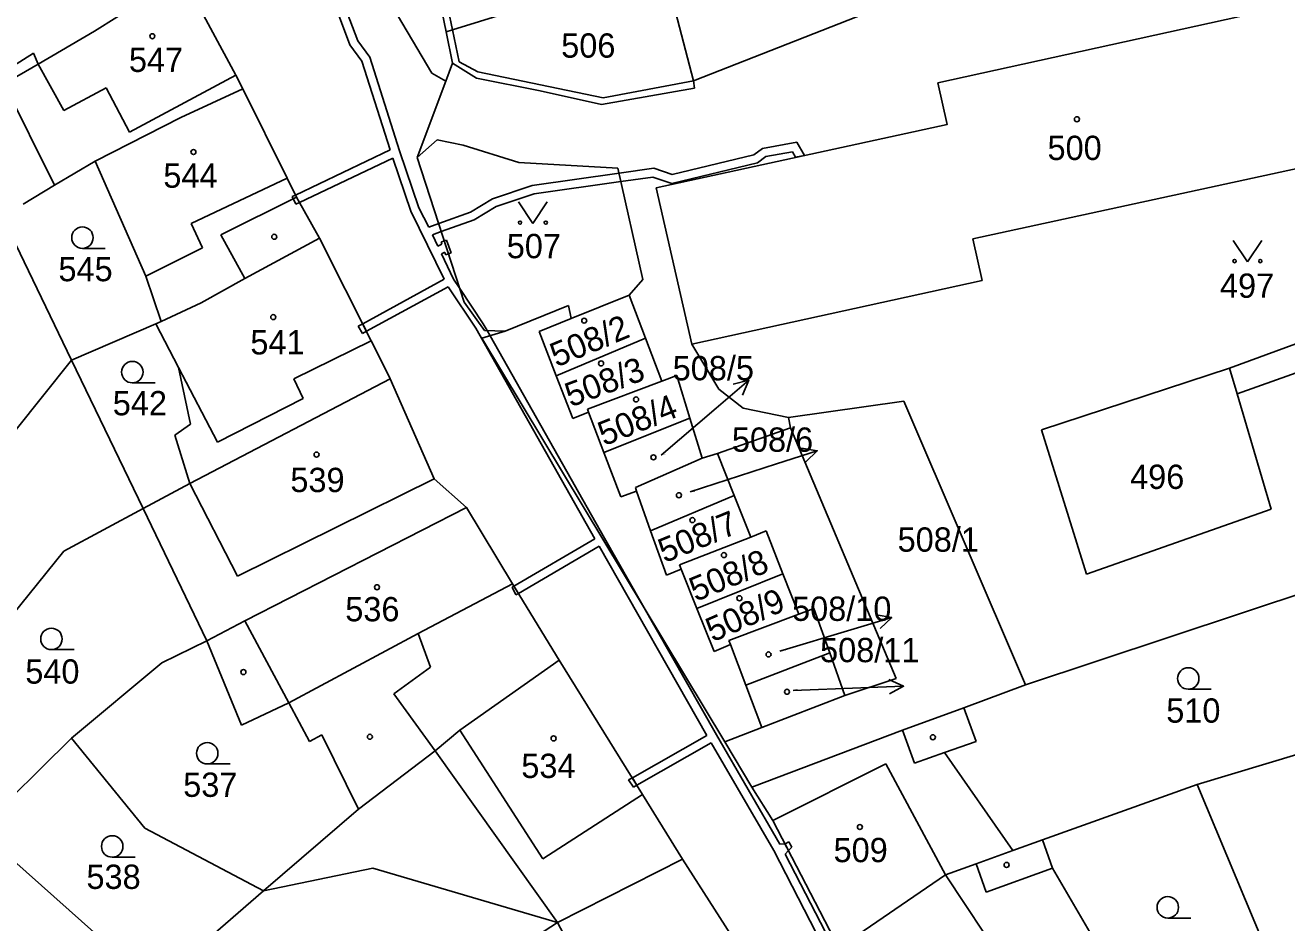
# Model space of a CAD drawing. Extents: x -785744 to -782822, y -1067550 to -1063910.
# Drawn here: x -783737.6 to -783649.3, y -1065623.4 to -1065560.7 of the extents above; entities that cross this region are included whole.
import ezdxf

# ---------------------------------------------------------------- set-up
doc = ezdxf.new("R2010")
doc.units = 0
for name, color, linetype in [('Hranice parcel', 7, 'Continuous'), ('Parcelní čísla', 7, 'Continuous'), ('Pop_ČP_popisy', 7, 'Continuous'), ('Vnitřní kresba', 7, 'Continuous'), ('Věcná břemena k části', 7, 'Continuous'), ('Značky budov', 7, 'Continuous'), ('Značky kultur', 7, 'Continuous')]:
    doc.layers.add(name, color=color, linetype=linetype)

msp = doc.modelspace()

# ---------------------------------------------------------------- linework, layer by layer
at = {"layer": 'Hranice parcel'}
for p, q in [((-783716.96, -1065575.54), (-783713.34, -1065582.73)), ((-783728.41, -1065581.54), (-783728.04, -1065581.38)), ((-783728.41, -1065581.54), (-783734.31, -1065584.09)), ((-783726.82, -1065584.6), (-783728.41, -1065581.54)), ((-783713.34, -1065582.73), (-783712.51, -1065584.38)), ((-783726.82, -1065584.6), (-783726, -1065588.56))]:
    msp.add_line(p, q, dxfattribs=at)
for points in [[(-783692.88, -1065556.48), (-783690.8, -1065564.53)], [(-783726.53, -1065557.25), (-783722.81, -1065564.14)], [(-783707.66, -1065560.97), (-783695.33, -1065557.14)], [(-783673.7, -1065564.67), (-783639.49, -1065557.16)], [(-783732.71, -1065561.07), (-783728.03, -1065558.1)], [(-783708.71, -1065558.16), (-783708.1, -1065561.11)], [(-783690.8, -1065564.53), (-783675.21, -1065558.4)], [(-783736.66, -1065563.38), (-783732.71, -1065561.07)], [(-783708.1, -1065561.11), (-783707.66, -1065560.97)], [(-783708.1, -1065561.11), (-783707.65, -1065563.31)], [(-783739.35, -1065564.1), (-783736.98, -1065562.6)], [(-783736.98, -1065562.6), (-783736.66, -1065563.38)], [(-783739.03, -1065564.74), (-783736.66, -1065563.38)], [(-783708.12, -1065564.56), (-783707.65, -1065563.31)], [(-783707.65, -1065563.31), (-783705.98, -1065564.35)], [(-783722.81, -1065564.14), (-783722.33, -1065565.09)], [(-783710.12, -1065569.9), (-783708.12, -1065564.56)], [(-783705.98, -1065564.35), (-783701.52, -1065565.23)], [(-783693.41, -1065572.02), (-783673.04, -1065567.59), (-783673.7, -1065564.67)], [(-783690.8, -1065564.53), (-783690.72, -1065565.05)], [(-783739.03, -1065564.74), (-783735.5, -1065571.85)], [(-783726.66, -1065567.1), (-783722.33, -1065565.09)], [(-783722.33, -1065565.09), (-783719.23, -1065571.34)], [(-783701.52, -1065565.23), (-783697.22, -1065566.19)], [(-783697.22, -1065566.19), (-783690.72, -1065565.05)], [(-783732.67, -1065570.15), (-783726.66, -1065567.1)], [(-783671.24, -1065575.59), (-783637.06, -1065568.18)], [(-783710.12, -1065569.9), (-783708.72, -1065568.67)], [(-783708.72, -1065568.67), (-783706.9, -1065569.03)], [(-783706.9, -1065569.03), (-783703.01, -1065570.26)], [(-783710.12, -1065569.9), (-783706.84, -1065580.03)], [(-783735.5, -1065571.85), (-783732.67, -1065570.15)], [(-783732.67, -1065570.15), (-783729.12, -1065578.2)], [(-783703.01, -1065570.26), (-783696.08, -1065570.65)], [(-783696.08, -1065570.65), (-783694.34, -1065578.44)], [(-783719.23, -1065571.34), (-783718.58, -1065572.68)], [(-783737.69, -1065573.18), (-783735.5, -1065571.85)], [(-783693.41, -1065572.02), (-783690.91, -1065582.97)], [(-783718.58, -1065572.68), (-783716.96, -1065575.54)], [(-783738.82, -1065574.73), (-783734.31, -1065584.09)], [(-783722.18, -1065578.36), (-783716.96, -1065575.54)], [(-783671.24, -1065575.59), (-783670.59, -1065578.52)], [(-783729.12, -1065578.2), (-783728.04, -1065581.38)], [(-783725.25, -1065580.06), (-783722.18, -1065578.36)], [(-783695.29, -1065579.53), (-783694.34, -1065578.44)], [(-783690.91, -1065582.97), (-783670.59, -1065578.52)], [(-783699.35, -1065581.17), (-783695.29, -1065579.53)], [(-783695.29, -1065579.53), (-783694.14, -1065582.54)], [(-783728.04, -1065581.38), (-783725.25, -1065580.06)], [(-783706.84, -1065580.03), (-783705.41, -1065582)], [(-783703.98, -1065582.06), (-783699.55, -1065580.25)], [(-783699.55, -1065580.25), (-783699.35, -1065581.17)], [(-783701.6, -1065582.08), (-783699.35, -1065581.17)], [(-783705.6, -1065582.54), (-783703.98, -1065582.06)], [(-783705.41, -1065582), (-783703.98, -1065582.06)], [(-783701.6, -1065582.08), (-783700.4, -1065585.17)], [(-783705.6, -1065582.54), (-783688.61, -1065610.77)], [(-783700.4, -1065585.17), (-783694.14, -1065582.54)], [(-783694.14, -1065582.54), (-783693, -1065585.54)], [(-783690.91, -1065582.97), (-783689.01, -1065586.1)], [(-783751.85, -1065606.03), (-783734.31, -1065584.09)], [(-783734.31, -1065584.09), (-783729.3, -1065594.46)], [(-783712.51, -1065584.38), (-783712.01, -1065585.39)], [(-783666.45, -1065588.96), (-783653.29, -1065584.63)], [(-783653.29, -1065584.63), (-783652.75, -1065586.43)], [(-783726.03, -1065592.7), (-783712.01, -1065585.39)], [(-783712.01, -1065585.39), (-783708.94, -1065592.38)], [(-783700.4, -1065585.17), (-783699.24, -1065588.16)], [(-783698.21, -1065587.51), (-783693, -1065585.54)], [(-783693, -1065585.54), (-783691.96, -1065585.15)], [(-783691.96, -1065585.15), (-783691.04, -1065588.15)], [(-783689.01, -1065586.1), (-783687.32, -1065587.43)], [(-783652.75, -1065586.43), (-783650.38, -1065594.51)], [(-783698.21, -1065587.51), (-783698.13, -1065587.73)], [(-783687.32, -1065587.43), (-783684.14, -1065588.1)], [(-783684.14, -1065588.1), (-783676.07, -1065586.95)], [(-783676.07, -1065586.95), (-783667.55, -1065606.8)], [(-783699.24, -1065588.16), (-783698.13, -1065587.73)], [(-783698.13, -1065587.73), (-783697.06, -1065590.53)], [(-783697.06, -1065590.53), (-783691.04, -1065588.15)], [(-783691.04, -1065588.15), (-783690.19, -1065590.94)], [(-783684.14, -1065588.1), (-783684.01, -1065588.82)], [(-783727.08, -1065589.33), (-783726, -1065588.56)], [(-783727.08, -1065589.33), (-783726.03, -1065592.7)], [(-783689.11, -1065590.62), (-783684.01, -1065588.82)], [(-783666.45, -1065588.96), (-783663.3, -1065599.05)], [(-783697.06, -1065590.53), (-783695.88, -1065593.64)], [(-783694.85, -1065592.99), (-783690.19, -1065590.94)], [(-783690.19, -1065590.94), (-783689.11, -1065590.62)], [(-783689.11, -1065590.62), (-783687.95, -1065593.54)], [(-783729.3, -1065594.46), (-783726.03, -1065592.7)], [(-783708.94, -1065592.38), (-783706.67, -1065594.39)], [(-783695.88, -1065593.64), (-783694.77, -1065593.24)], [(-783694.85, -1065592.99), (-783694.77, -1065593.24)], [(-783694.77, -1065593.24), (-783693.79, -1065596.01)], [(-783693.79, -1065596.01), (-783687.95, -1065593.54)], [(-783687.95, -1065593.54), (-783686.79, -1065596.46)], [(-783734.85, -1065597.44), (-783729.3, -1065594.46)], [(-783729.3, -1065594.46), (-783724.85, -1065603.71)], [(-783722.19, -1065602.31), (-783706.67, -1065594.39)], [(-783706.67, -1065594.39), (-783703.45, -1065599.73)], [(-783663.3, -1065599.05), (-783650.38, -1065594.51)], [(-783693.79, -1065596.01), (-783692.69, -1065599.13)], [(-783691.78, -1065598.41), (-783686.79, -1065596.46)], [(-783686.79, -1065596.46), (-783685.71, -1065596.03)], [(-783685.71, -1065596.03), (-783684.53, -1065599.03)], [(-783745.75, -1065610.93), (-783734.85, -1065597.44)], [(-783692.69, -1065599.13), (-783691.66, -1065598.71)], [(-783691.78, -1065598.41), (-783691.66, -1065598.71)], [(-783691.66, -1065598.71), (-783690.55, -1065601.46)], [(-783690.55, -1065601.46), (-783684.53, -1065599.03)], [(-783684.53, -1065599.03), (-783683.42, -1065601.86)], [(-783667.55, -1065606.8), (-783642.32, -1065598.43)], [(-783703.45, -1065599.73), (-783700.19, -1065605.06)], [(-783690.55, -1065601.46), (-783689.34, -1065604.47)], [(-783683.42, -1065601.86), (-783682.36, -1065601.45)], [(-783682.36, -1065601.45), (-783681.26, -1065604.55)], [(-783724.85, -1065603.71), (-783722.19, -1065602.31)], [(-783688.31, -1065603.7), (-783683.42, -1065601.86)], [(-783727.99, -1065605.25), (-783724.85, -1065603.71)], [(-783724.85, -1065603.71), (-783722.42, -1065609.61)], [(-783689.34, -1065604.47), (-783688.2, -1065603.98)], [(-783688.31, -1065603.7), (-783688.2, -1065603.98)], [(-783688.2, -1065603.98), (-783687.13, -1065606.82)], [(-783734.32, -1065610.53), (-783727.99, -1065605.25)], [(-783707.14, -1065609.96), (-783700.19, -1065605.06)], [(-783700.19, -1065605.06), (-783694.35, -1065614.47)], [(-783687.13, -1065606.82), (-783681.26, -1065604.55)], [(-783681.26, -1065604.55), (-783680.2, -1065607.55)], [(-783687.13, -1065606.82), (-783686.02, -1065609.78)], [(-783671.88, -1065608.41), (-783667.55, -1065606.8)], [(-783686.02, -1065609.78), (-783680.2, -1065607.55)], [(-783722.42, -1065609.61), (-783719.12, -1065608.06)], [(-783719.12, -1065608.06), (-783717.67, -1065610.76)], [(-783676.16, -1065609.96), (-783671.88, -1065608.41)], [(-783671.88, -1065608.41), (-783671.02, -1065610.76)], [(-783655.55, -1065613.76), (-783638.72, -1065608.7)], [(-783740.75, -1065616.87), (-783734.32, -1065610.53)], [(-783734.32, -1065610.53), (-783729.19, -1065616.81)], [(-783717.67, -1065610.76), (-783716.79, -1065610.28)], [(-783716.79, -1065610.28), (-783714.24, -1065615.48)], [(-783708.86, -1065611.42), (-783707.14, -1065609.96)], [(-783686.7, -1065613.96), (-783676.16, -1065609.96)], [(-783714.24, -1065615.48), (-783708.86, -1065611.42)], [(-783688.61, -1065610.77), (-783686.7, -1065613.96)], [(-783673.23, -1065611.53), (-783671.02, -1065610.76)], [(-783673.23, -1065611.53), (-783668.44, -1065618.38)], [(-783686.7, -1065613.96), (-783685.23, -1065616.29)], [(-783666.37, -1065617.64), (-783655.55, -1065613.76)], [(-783655.55, -1065613.76), (-783649.44, -1065628.38)], [(-783694.35, -1065614.47), (-783691.55, -1065619)], [(-783720.87, -1065621.21), (-783714.24, -1065615.48)], [(-783685.23, -1065616.29), (-783680.61, -1065625.18)], [(-783740.32, -1065617.38), (-783731.67, -1065625.04)], [(-783729.19, -1065616.81), (-783720.87, -1065621.21)], [(-783668.44, -1065618.38), (-783666.37, -1065617.64)], [(-783666.37, -1065617.64), (-783665.66, -1065619.61)], [(-783671.02, -1065619.31), (-783668.44, -1065618.38)], [(-783700.3, -1065623.43), (-783691.55, -1065619)], [(-783691.55, -1065619), (-783686.72, -1065626.56)], [(-783673.15, -1065620.08), (-783671.02, -1065619.31)], [(-783720.87, -1065621.21), (-783713.22, -1065619.62)], [(-783713.22, -1065619.62), (-783700.3, -1065623.43)], [(-783680.61, -1065625.18), (-783673.15, -1065620.08)], [(-783665.66, -1065619.61), (-783658.15, -1065632.49)], [(-783728.52, -1065627.83), (-783720.87, -1065621.21)], [(-783705.51, -1065626.79), (-783700.3, -1065623.43)], [(-783700.3, -1065623.43), (-783696.36, -1065630.89)]]:
    msp.add_lwpolyline(points, dxfattribs=at)
at = {"layer": 'Pop_ČP_popisy'}
for p, q in [((-783689.21, -1065587.44), (-783686.929, -1065585.491)), ((-783684.98, -1065591.34), (-783682.127, -1065590.413)), ((-783679.79, -1065602.95), (-783676.915, -1065602.092)), ((-783679.09, -1065607.01), (-783676.092, -1065606.89))]:
    msp.add_line(p, q, dxfattribs=at)
for points in [[(-783688.014, -1065585.761), (-783686.929, -1065585.491), (-783687.365, -1065586.521)], [(-783693.05, -1065590.72), (-783689.21, -1065587.44)], [(-783683.232, -1065590.247), (-783682.127, -1065590.413), (-783682.923, -1065591.198)], [(-783691.03, -1065593.3), (-783684.98, -1065591.34)], [(-783678.017, -1065601.899), (-783676.915, -1065602.092), (-783677.731, -1065602.857)], [(-783684.75, -1065604.43), (-783679.79, -1065602.95)], [(-783683.82, -1065607.2), (-783679.09, -1065607.01)], [(-783677.112, -1065606.43), (-783676.092, -1065606.89), (-783677.072, -1065607.429)]]:
    msp.add_lwpolyline(points, dxfattribs=at)
at = {"layer": 'Vnitřní kresba'}
for p, q in [((-783713.34, -1065582.73), (-783718.76, -1065585.39)), ((-783724.11, -1065589.82), (-783726.82, -1065584.6)), ((-783718.76, -1065585.39), (-783718.11, -1065586.76)), ((-783718.11, -1065586.76), (-783724.11, -1065589.82))]:
    msp.add_line(p, q, dxfattribs=at)
for points in [[(-783708.26, -1065558.07), (-783707.66, -1065560.97)], [(-783712.18, -1065558.78), (-783709.11, -1065564)], [(-783707.66, -1065560.97), (-783707.2, -1065563.21)], [(-783736.66, -1065563.38), (-783734.86, -1065566.62)], [(-783707.2, -1065563.21), (-783705.88, -1065563.91)], [(-783730.26, -1065568.13), (-783722.81, -1065564.14)], [(-783709.11, -1065564), (-783708.12, -1065564.56)], [(-783705.88, -1065563.91), (-783697.12, -1065565.74)], [(-783697.12, -1065565.74), (-783690.8, -1065564.53)], [(-783734.86, -1065566.62), (-783731.88, -1065565.04)], [(-783731.88, -1065565.04), (-783730.26, -1065568.13)], [(-783725.94, -1065574.53), (-783719.23, -1065571.34)], [(-783723.87, -1065575.32), (-783718.58, -1065572.68)], [(-783725.94, -1065574.53), (-783725.14, -1065576.23)], [(-783723.87, -1065575.32), (-783722.18, -1065578.36)], [(-783729.12, -1065578.2), (-783725.14, -1065576.23)], [(-783653.29, -1065584.63), (-783634.71, -1065577.84)], [(-783652.75, -1065586.43), (-783634.47, -1065579.93)], [(-783684.01, -1065588.82), (-783676.6, -1065606.35)], [(-783726.03, -1065592.7), (-783722.71, -1065599.19)], [(-783722.71, -1065599.19), (-783708.94, -1065592.38)], [(-783710.05, -1065603.2), (-783703.45, -1065599.73)], [(-783722.19, -1065602.31), (-783719.12, -1065608.06)], [(-783719.12, -1065608.06), (-783710.05, -1065603.2)], [(-783710.05, -1065603.2), (-783709.2, -1065605.55)], [(-783711.77, -1065607.43), (-783709.2, -1065605.55)], [(-783680.2, -1065607.55), (-783676.6, -1065606.35)], [(-783711.77, -1065607.43), (-783708.86, -1065611.42)], [(-783707.14, -1065609.96), (-783701.33, -1065618.97)], [(-783688.61, -1065610.77), (-783686.02, -1065609.78)], [(-783676.16, -1065609.96), (-783675.32, -1065612.27)], [(-783708.86, -1065611.42), (-783700.3, -1065623.43)], [(-783685.23, -1065616.29), (-783677.33, -1065612.31)], [(-783677.33, -1065612.31), (-783673.15, -1065620.08)], [(-783675.32, -1065612.27), (-783673.23, -1065611.53)], [(-783701.33, -1065618.97), (-783694.35, -1065614.47)], [(-783671.02, -1065619.31), (-783670.31, -1065621.29)], [(-783673.15, -1065620.08), (-783664.99, -1065632.4)], [(-783670.31, -1065621.29), (-783665.66, -1065619.61)]]:
    msp.add_lwpolyline(points, dxfattribs=at)
at = {"layer": 'Věcná břemena k části'}
for points in [[(-783714.29, -1065561.75), (-783715.84, -1065557.61)], [(-783716.42, -1065557.75), (-783714.83, -1065562.03)], [(-783714.83, -1065562.03), (-783713.99, -1065563.16)], [(-783713.45, -1065562.88), (-783714.29, -1065561.75)], [(-783711.37, -1065569.44), (-783713.45, -1065562.88)], [(-783713.99, -1065563.16), (-783712.02, -1065569.37)], [(-783683.56, -1065568.84), (-783685.96, -1065569.28)], [(-783683.03, -1065569.76), (-783683.56, -1065568.84)], [(-783712.02, -1065569.37), (-783718.65, -1065572.53)], [(-783718.36, -1065573.06), (-783711.83, -1065569.95)], [(-783711.83, -1065569.95), (-783710.56, -1065573.67)], [(-783710, -1065573.43), (-783711.37, -1065569.44)], [(-783686.57, -1065569.71), (-783692.28, -1065571.1)], [(-783685.96, -1065569.28), (-783686.57, -1065569.71)], [(-783686.31, -1065570.27), (-783685.72, -1065569.84)], [(-783685.72, -1065569.84), (-783683.87, -1065569.51)], [(-783683.87, -1065569.51), (-783683.65, -1065569.89)], [(-783683.65, -1065569.89), (-783683.03, -1065569.76)], [(-783693.57, -1065570.66), (-783696, -1065571)], [(-783692.28, -1065571.1), (-783693.57, -1065570.66)], [(-783692.3, -1065571.72), (-783686.31, -1065570.27)], [(-783696, -1065571), (-783702.09, -1065571.86)], [(-783701.95, -1065572.44), (-783695.87, -1065571.59)], [(-783695.87, -1065571.59), (-783693.63, -1065571.28)], [(-783693.63, -1065571.28), (-783692.3, -1065571.72)], [(-783718.65, -1065572.53), (-783718.88, -1065572.64)], [(-783718.88, -1065572.64), (-783718.61, -1065573.18)], [(-783718.65, -1065572.53), (-783718.58, -1065572.68)], [(-783718.58, -1065572.68), (-783718.65, -1065572.53)], [(-783702.09, -1065571.86), (-783704.85, -1065572.8)], [(-783704.59, -1065573.34), (-783701.95, -1065572.44)], [(-783718.61, -1065573.18), (-783718.36, -1065573.06)], [(-783718.58, -1065572.68), (-783718.36, -1065573.06)], [(-783718.36, -1065573.06), (-783718.58, -1065572.68)], [(-783709.32, -1065574.78), (-783710, -1065573.43)], [(-783704.85, -1065572.8), (-783706.39, -1065573.72)], [(-783706.13, -1065574.26), (-783704.59, -1065573.34)], [(-783710.56, -1065573.67), (-783708.25, -1065578.41)], [(-783706.39, -1065573.72), (-783708.62, -1065574.53)], [(-783708.44, -1065575.09), (-783706.13, -1065574.26)], [(-783708.62, -1065574.53), (-783709.32, -1065574.78)], [(-783709.06, -1065575.32), (-783708.44, -1065575.09)], [(-783708.68, -1065576.11), (-783709.06, -1065575.32)], [(-783708.41, -1065575.97), (-783708.68, -1065576.11)], [(-783708.23, -1065575.74), (-783708.46, -1065575.83)], [(-783708.46, -1065575.83), (-783708.41, -1065575.97)], [(-783708.08, -1065575.69), (-783708.23, -1065575.74)], [(-783707.76, -1065576.57), (-783708.08, -1065575.69)], [(-783708.43, -1065576.64), (-783708.2, -1065576.53)], [(-783707.59, -1065578.41), (-783708.43, -1065576.64)], [(-783708.2, -1065576.53), (-783708.14, -1065576.71)], [(-783708.14, -1065576.71), (-783707.94, -1065576.64)], [(-783707.94, -1065576.64), (-783707.76, -1065576.57)], [(-783708.25, -1065578.41), (-783713.94, -1065581.53)], [(-783707.15, -1065579.07), (-783707.59, -1065578.41)], [(-783713.68, -1065582.06), (-783707.96, -1065578.94)], [(-783707.96, -1065578.94), (-783706.03, -1065581.85)], [(-783705.51, -1065581.53), (-783707.15, -1065579.07)], [(-783713.94, -1065581.53), (-783714.25, -1065581.7)], [(-783714.25, -1065581.7), (-783713.96, -1065582.22)], [(-783713.96, -1065582.22), (-783713.68, -1065582.06)], [(-783713.94, -1065581.53), (-783713.68, -1065582.06)], [(-783713.68, -1065582.06), (-783713.94, -1065581.53)], [(-783706.03, -1065581.85), (-783697.7, -1065596.58)], [(-783705.24, -1065582.01), (-783705.51, -1065581.53)], [(-783705.03, -1065582.37), (-783705.24, -1065582.01)], [(-783697.03, -1065596.54), (-783705.03, -1065582.37)], [(-783697.7, -1065596.58), (-783703.36, -1065599.88)], [(-783703.04, -1065600.4), (-783697.4, -1065597.1)], [(-783697.4, -1065597.1), (-783689.86, -1065610.33)], [(-783694.43, -1065601.09), (-783697.03, -1065596.54)], [(-783703.36, -1065599.88), (-783703.47, -1065599.95)], [(-783703.47, -1065599.95), (-783703.22, -1065600.5)], [(-783703.36, -1065599.88), (-783703.04, -1065600.4)], [(-783703.04, -1065600.4), (-783703.36, -1065599.88)], [(-783703.22, -1065600.5), (-783703.04, -1065600.4)], [(-783689.19, -1065610.29), (-783694.43, -1065601.09)], [(-783689.86, -1065610.33), (-783695.07, -1065613.3)], [(-783684.75, -1065617.93), (-783689.19, -1065610.29)], [(-783694.75, -1065613.82), (-783689.56, -1065610.85)], [(-783689.56, -1065610.85), (-783685.18, -1065618.38)], [(-783695.07, -1065613.3), (-783695.33, -1065613.45)], [(-783695.33, -1065613.45), (-783695, -1065613.96)], [(-783695.07, -1065613.3), (-783694.75, -1065613.82)], [(-783694.75, -1065613.82), (-783695.07, -1065613.3)], [(-783695, -1065613.96), (-783694.75, -1065613.82)], [(-783685.18, -1065618.38), (-783681.34, -1065625.82)], [(-783684.38, -1065617.92), (-783684.75, -1065617.93)], [(-783684.13, -1065617.78), (-783684.38, -1065617.92)], [(-783684.14, -1065618.38), (-783684.38, -1065617.92)], [(-783684.38, -1065617.92), (-783684.14, -1065618.38)], [(-783684.38, -1065618.63), (-783684.14, -1065618.38)], [(-783684.14, -1065618.38), (-783683.92, -1065618.15)], [(-783683.92, -1065618.15), (-783684.13, -1065617.78)], [(-783680.84, -1065625.5), (-783684.38, -1065618.63)]]:
    msp.add_lwpolyline(points, dxfattribs=at)
at = {"layer": 'Značky budov'}
for centre in [(-783728.66, -1065561.42), (-783663.96, -1065567.23), (-783725.78, -1065569.52), (-783720.13, -1065575.45), (-783720.2, -1065581.07), (-783698.44, -1065581.32), (-783697.26, -1065584.31), (-783694.81, -1065586.83), (-783717.17, -1065590.69), (-783693.6, -1065590.88), (-783691.81, -1065593.53), (-783690.87, -1065595.27), (-783688.66, -1065597.72), (-783712.94, -1065599.97), (-783687.58, -1065600.74), (-783685.54, -1065604.67), (-783722.29, -1065605.9), (-783684.25, -1065607.28), (-783713.44, -1065610.43), (-783700.58, -1065610.54), (-783674.04, -1065610.46), (-783679.15, -1065616.74), (-783668.88, -1065619.39)]:
    msp.add_circle(centre, 0.175, dxfattribs=at)
at = {"layer": 'Značky kultur'}
for p, q in [((-783703.03, -1065573.01), (-783702.03, -1065574.51)), ((-783702.03, -1065574.51), (-783701.03, -1065573.01)), ((-783653.03, -1065575.7), (-783652.03, -1065577.2)), ((-783652.03, -1065577.2), (-783651.03, -1065575.7)), ((-783733.55, -1065576.26), (-783731.95, -1065576.26)), ((-783730.06, -1065585.67), (-783728.46, -1065585.67)), ((-783735.72, -1065604.33), (-783734.12, -1065604.33)), ((-783656.17, -1065607.1), (-783654.57, -1065607.1)), ((-783724.82, -1065612.33), (-783723.22, -1065612.33)), ((-783731.47, -1065618.85), (-783729.87, -1065618.85)), ((-783657.6, -1065623.11), (-783656, -1065623.11))]:
    msp.add_line(p, q, dxfattribs=at)
for centre, radius in [((-783702.93, -1065574.46), 0.112), ((-783701.13, -1065574.46), 0.112), ((-783733.55, -1065575.51), 0.75), ((-783652.93, -1065577.15), 0.112), ((-783651.13, -1065577.15), 0.112), ((-783730.06, -1065584.92), 0.75), ((-783735.72, -1065603.58), 0.75), ((-783656.17, -1065606.35), 0.75), ((-783724.82, -1065611.58), 0.75), ((-783731.47, -1065618.1), 0.75), ((-783657.6, -1065622.36), 0.75)]:
    msp.add_circle(centre, radius, dxfattribs=at)

# ---------------------------------------------------------------- texts
at = {"layer": 'Parcelní čísla'}
for s, height, p in [('506', 1.7, (-783700.05, -1065562.92)), ('547', 1.7, (-783730.3, -1065563.92)), ('500', 1.7, (-783666.02, -1065570.08)), ('544', 1.7, (-783727.89, -1065572.02)), ('507', 1.7, (-783703.86, -1065576.95)), ('545', 1.7, (-783735.23, -1065578.56)), ('497', 1.7, (-783653.95, -1065579.72)), ('541', 1.7, (-783721.8, -1065583.68)), ('542', 1.7, (-783731.43, -1065587.94)), ('508/5', 0.1, (-783693.05, -1065590.72)), ('539', 1.7, (-783719, -1065593.31)), ('496', 1.7, (-783660.24, -1065593.09)), ('508/6', 0.1, (-783691.03, -1065593.3)), ('508/1', 1.7, (-783676.51, -1065597.48)), ('536', 1.7, (-783715.16, -1065602.35)), ('508/10', 0.1, (-783684.75, -1065604.43)), ('540', 1.7, (-783737.55, -1065606.71)), ('508/11', 0.1, (-783683.82, -1065607.2)), ('510', 1.7, (-783657.71, -1065609.44)), ('534', 1.7, (-783702.84, -1065613.31)), ('537', 1.7, (-783726.5, -1065614.63)), ('509', 1.7, (-783680.99, -1065619.2)), ('538', 1.7, (-783733.27, -1065621.07))]:
    msp.add_text(s, height=height, dxfattribs=at).set_placement(p)
for s, rotation, p in [('508/2', 22.52061, (-783700.38, -1065584.6)), ('508/3', 20.42604, (-783699.39, -1065587.39)), ('508/4', 21.80142, (-783697.05, -1065590.11)), ('508/7', 22.29363, (-783692.82, -1065598.29)), ('508/8', 22.52061, (-783690.64, -1065601)), ('508/9', 23.81868, (-783689.45, -1065603.83))]:
    msp.add_text(s, height=1.7, rotation=rotation, dxfattribs=at).set_placement(p)
at = {"layer": 'Pop_ČP_popisy'}
for s, p in [('508/5', (-783692.248, -1065585.49)), ('508/6', (-783688.106, -1065590.49)), ('508/10', (-783683.895, -1065602.32)), ('508/11', (-783681.934, -1065605.21))]:
    msp.add_text(s, height=1.7, dxfattribs=at).set_placement(p)

doc.saveas('drawing.dxf')
